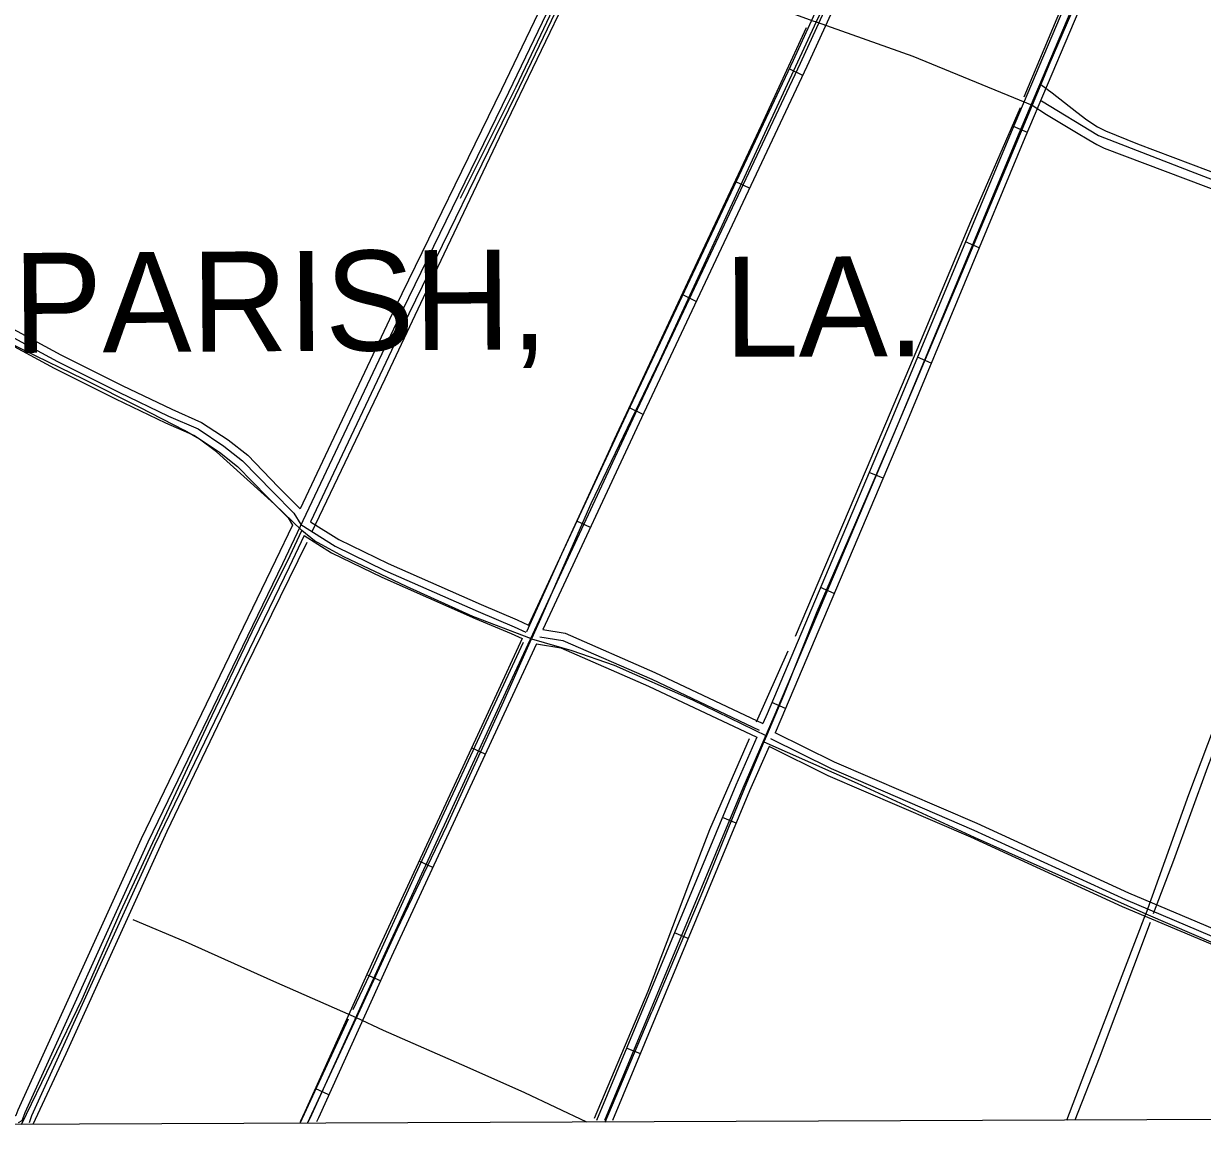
# Model space of a CAD drawing. Extents: x 3405885 to 3443815, y 558517 to 583997.
# Drawn here: x 3415002 to 3417362, y 563906 to 566129 of the extents above; entities that cross this region are included whole.
import ezdxf

# ---------------------------------------------------------------- set-up
doc = ezdxf.new("R2010")
doc.units = 0
for name, color, linetype in [('V-DTCH-CNTR', 7, 'Continuous'), ('V-GRID-FRAM', 7, 'Continuous'), ('V-ROAD-CNTR', 7, 'Continuous'), ('V-TOPO-GNAM-IDEN', 7, 'Continuous'), ('V-TOPO-SHOR', 7, 'Continuous')]:
    doc.layers.add(name, color=color, linetype=linetype)

msp = doc.modelspace()

# ---------------------------------------------------------------- linework, layer by layer
at = {"layer": 'V-DTCH-CNTR'}
for points in [[(3417302.4, 567666.9), (3417211.4, 567491.3), (3417056.5, 567153.8), (3416943.8, 566895.3), (3416932.8, 566871.6), (3416922.1, 566847.6), (3416829.7, 566641.3), (3416662.2, 566281.6), (3416589.1, 566131.9), (3416464.6, 565864), (3416275.4, 565453.5), (3416137.5, 565167.4), (3416034.5, 564931.6), (3416019, 564897.5)], [(3417610.8, 567337.5), (3417525.2, 567138.1), (3417513.3, 567110.2), (3417415.8, 566882.9), (3417344.8, 566720.2), (3417335.4, 566698.5), (3417329.4, 566685.1), (3417241.9, 566487.9), (3417145.1, 566255.7), (3417054.7, 566045.2), (3417038.6, 566006.8), (3417021.4, 565965.7), (3416973.2, 565850.9), (3416874.6, 565615.6), (3416744.7, 565309.8), (3416665.5, 565124.8), (3416590.4, 564951.7), (3416523.3, 564784.2), (3416489.2, 564703.3), (3416484.1, 564691.3), (3416445.9, 564600.6), (3416361.1, 564391.4), (3416260.1, 564151.2)], [(3416510.9, 567225.1), (3416532.6, 567208.2), (3416536.1, 567204.9), (3416539, 567198), (3416542.8, 567182.2), (3416542.3, 567172.6), (3416541, 567167.7), (3416538.4, 567160.8), (3416389.1, 566854.3), (3416219.4, 566497.9), (3416110.2, 566261.2), (3415987.6, 566001.5), (3415876.1, 565778.6)], [(3416158.8, 566298.4), (3416334.3, 566225.2), (3416582.5, 566134.3), (3416589.1, 566131.9), (3416782.1, 566063.4), (3417021.4, 565965.7)], [(3417038.6, 566006.8), (3417061.1, 565989.9), (3417110.5, 565951.2), (3417130.9, 565936.3), (3417152.1, 565922.2), (3417168.2, 565914.1)], [(3417021.4, 565965.7), (3417050.2, 565946.8), (3417110, 565910.5), (3417134.6, 565895.7), (3417150.7, 565887), (3417165.5, 565879.6), (3417409.7, 565787.1), (3417668.1, 565684.4), (3417724.1, 565659.8), (3417729.1, 565655), (3417730.5, 565653), (3417731.3, 565648.1), (3417703.1, 565563.5), (3417570.8, 565220.5), (3417461.9, 564923.1), (3417334.4, 564585.1), (3417249, 564346.9)], [(3417168.2, 565914.1), (3417231.9, 565888.3), (3417444, 565808.3)], [(3414998.3, 563925.6), (3415119.6, 564176.6), (3415196.2, 564351.2), (3415372.2, 564728.7), (3415460.1, 564911.3), (3415536.2, 565064.1), (3415559.1, 565114), (3415504.7, 565167.2), (3415388.6, 565271.4), (3415354.3, 565297.2), (3415324.5, 565314.2), (3415234.8, 565360.2), (3415121.9, 565417.4), (3415003.9, 565474.6), (3414878.6, 565537.6), (3414836.4, 565560.4), (3414707.6, 565626.3)], [(3415750.2, 564315.7), (3415849.7, 564523.2), (3415963.9, 564772.7), (3416019, 564897.5), (3415901.6, 564942), (3415768.6, 565001.9), (3415643.1, 565061.3), (3415584.9, 565093.8), (3415559.1, 565114)], [(3416019, 564897.5), (3416099.9, 564873.8), (3416184.4, 564844.8)], [(3416184.4, 564844.8), (3416341.3, 564775.5), (3416489.2, 564703.3)], [(3416484.1, 564691.3), (3416671, 564608.4), (3416905.3, 564500.6), (3417249, 564346.9), (3417436.1, 564266.3), (3417594.5, 564198.1), (3417652.8, 564172.9), (3417876.8, 564085.9), (3418078.3, 564014.4), (3418273.5, 563938.7)], [(3416129.6, 563930.1), (3416005.8, 563989), (3415889.9, 564040.4), (3415723, 564113.9), (3415668.8, 564138.7), (3415503, 564211.9), (3415326.3, 564291.3), (3415221.7, 564335.3)], [(3417090.9, 563934), (3417126.7, 564029.2), (3417249, 564346.9)], [(3415570.4, 563927.9), (3415668.8, 564138.7), (3415672.3, 564146.4), (3415750.2, 564315.7)], [(3416166.6, 563930.3), (3416260.1, 564151.2)]]:
    msp.add_lwpolyline(points, dxfattribs=at)
at = {"layer": 'V-GRID-FRAM'}
msp.add_lwpolyline([(3409954, 582088.9), (3441575.2, 582215.4), (3441655.9, 564032.2), (3410018.8, 563905.7), (3409954, 582088.9)], dxfattribs=at)
at = {"layer": 'V-ROAD-CNTR'}
for p, q in [((3416562, 566025.1), (3416534.9, 566037.9)), ((3417011.6, 565910.8), (3416984, 565922.5)), ((3416455.5, 565799), (3416428.3, 565811.7)), ((3416915.5, 565680.1), (3416887.8, 565691.6)), ((3416348.9, 565572.8), (3416321.8, 565585.6)), ((3416819.4, 565449.3), (3416791.7, 565460.8)), ((3416242.4, 565346.7), (3416215.2, 565359.4)), ((3416722.7, 565218.7), (3416695.1, 565230.4)), ((3416137, 565120), (3416109.8, 565132.7)), ((3416625.2, 564988.5), (3416597.6, 565000.2)), ((3416527.8, 564758.2), (3416500.1, 564769.9)), ((3415926.3, 564666.6), (3415899, 564679.2)), ((3416428.9, 564528.7), (3416401.2, 564540.2)), ((3415821.2, 564439.8), (3415793.9, 564452.4)), ((3416332.9, 564297.9), (3416305.2, 564309.4)), ((3415716.5, 564212.9), (3415689.2, 564225.3)), ((3416236.9, 564067.1), (3416209.2, 564078.6)), ((3415613.4, 563985.1), (3415586.1, 563997.5))]:
    msp.add_line(p, q, dxfattribs=at)
for points in [[(3418009.6, 568256.7), (3417948.1, 568084), (3417784.8, 567724.8), (3417633.8, 567379), (3417470.5, 567008.8), (3417261.3, 566539.3), (3416993.1, 565905.5), (3416751, 565323.9), (3416504.4, 564741.6), (3416441.9, 564598.9), (3416165.1, 563933.5)], [(3418023.8, 568251.7), (3417962.1, 568078.4), (3417798.5, 567718.7), (3417647.5, 567372.9), (3417484.2, 567002.8), (3417275.1, 566533.4), (3417006.9, 565899.7), (3416764.8, 565318.1), (3416518.2, 564735.7), (3416506.7, 564709.5)], [(3415779.8, 567653.6), (3415947.5, 567565.5), (3416277.7, 567377), (3416503.8, 567239.2), (3416549.6, 567203.3), (3416538.7, 567159.5), (3416392.9, 566873), (3416158.2, 566377.3), (3415972.7, 565990.5), (3415759.9, 565554.1), (3415520.2, 565047.4), (3415251, 564490.5), (3415004.4, 563948.6), (3414999, 563932.9), (3414991.3, 563928.8)], [(3417300.7, 567666.7), (3417148.8, 567344.9), (3416899.5, 566797.7), (3416556.6, 566048.8), (3416230.4, 565356.4), (3415958.4, 564771.7), (3415725.1, 564268), (3415578.7, 563944.9), (3415572.2, 563931.1)], [(3417282.4, 567663.1), (3417135.2, 567351.2), (3416885.8, 566804), (3416543, 566055.1), (3416216.8, 565362.7), (3416013.2, 564925)], [(3417306.3, 567643.4), (3417162.4, 567338.6), (3416913.1, 566791.5), (3416570.2, 566042.5), (3416244, 565350), (3416042, 564915.8)], [(3417653.7, 567462.1), (3417620.1, 567385), (3417456.8, 567014.9), (3417247.5, 566545.3), (3416979.3, 565911.3), (3416737.1, 565329.7), (3416490.6, 564747.5), (3416482.2, 564728.2)], [(3416105.9, 566302.9), (3415959.2, 565997), (3415746.4, 565560.6), (3415555.7, 565157.6)], [(3416139.1, 566302.7), (3415986.2, 565984), (3415773.4, 565547.6), (3415576.7, 565131.7)], [(3414721.7, 565627.2), (3414775.7, 565603.8), (3414918.1, 565534.7), (3415070.2, 565452.7), (3415192.8, 565391), (3415292.6, 565343.2), (3415351.4, 565317.4), (3415403, 565283.3), (3415440.7, 565253.7), (3415501.4, 565191.3), (3415543.5, 565148.6), (3415556.9, 565126.5), (3415626, 565082.7), (3415725.7, 565034.5), (3415912.4, 564952.1), (3415984.4, 564921.5), (3416007.8, 564910.9)], [(3414730.8, 565639.6), (3414781.9, 565617.4), (3414924.9, 565548), (3415077.1, 565466), (3415199.4, 565404.5), (3415298.9, 565356.8), (3415358.6, 565330.6), (3415411.8, 565295.5), (3415450.8, 565264.8), (3415512.1, 565201.8), (3415555.7, 565157.6)], [(3414717, 565612.9), (3414769.4, 565590.2), (3414911.2, 565521.3), (3415063.2, 565439.4), (3415186.2, 565377.6), (3415286.4, 565329.6), (3415344.2, 565304.2), (3415394.3, 565271.1), (3415430.7, 565242.5), (3415490.7, 565180.8), (3415531.6, 565139.3), (3415540.3, 565125)], [(3415576.7, 565131.7), (3415633.3, 565095.9), (3415732, 565048.1), (3415918.4, 564965.9), (3415990.4, 564935.2), (3416013.2, 564925)], [(3415540.3, 565125), (3415506.6, 565053.9), (3415237.4, 564496.9), (3414990.4, 563954.2), (3414986.7, 563943.3), (3414984.2, 563942)], [(3415563.7, 565104.4), (3415533.7, 565040.9), (3415264.6, 564484.2), (3415018.3, 563943.1), (3415013.4, 563928.9)], [(3415563.7, 565104.4), (3415618.7, 565069.6), (3415719.4, 565020.9), (3415906.4, 564938.3), (3415978.3, 564907.8), (3416000.5, 564897.8)], [(3416042, 564915.8), (3416086.3, 564908.5), (3416265.9, 564830.1), (3416482.2, 564728.2)], [(3416000.5, 564897.8), (3415944.8, 564778), (3415711.4, 564274.3), (3415565.1, 563951.2), (3415555.6, 563931)], [(3416035.8, 564901.6), (3416082, 564894), (3416259.7, 564816.4), (3416474.9, 564715)], [(3416028.9, 564887.6), (3415972, 564765.4), (3415738.7, 564261.8), (3415592.3, 563938.6), (3415588.8, 563931.2)], [(3416028.9, 564887.6), (3416077.7, 564879.5), (3416253.5, 564802.8), (3416470.1, 564700.7)], [(3417591, 564231.3), (3417506.9, 564265.1), (3417214.5, 564388.7), (3416911, 564527.9), (3416625.6, 564650.8), (3416506.7, 564709.5)], [(3416470.1, 564700.7), (3416428.1, 564604.8), (3416148.8, 563933.4)], [(3416494.7, 564682), (3416455.7, 564593), (3416181.4, 563933.5)], [(3417580.9, 564203.1), (3417495.5, 564237.4), (3417202.4, 564361.3), (3416898.8, 564500.5), (3416613.1, 564623.6), (3416494.7, 564682)], [(3417589.7, 564215.7), (3417501.2, 564251.3), (3417208.5, 564375), (3416904.9, 564514.2), (3416619.3, 564637.2), (3416498, 564697)]]:
    msp.add_lwpolyline(points, dxfattribs=at)
at = {"layer": 'V-TOPO-SHOR'}
msp.add_line((3416532.4, 564873), (3416468.9, 564730.6), dxfattribs=at)
for points in [[(3417311, 566686.8), (3417195.7, 566425.9), (3417102.2, 566214.1), (3417004.4, 565981.6)], [(3416189.8, 566395.8), (3416098.4, 566200.3), (3415961.2, 565914.3), (3415824.3, 565626.5), (3415725.5, 565417), (3415579, 565111.4)], [(3417958.5, 566199.4), (3417762, 565668.3), (3417757.8, 565657), (3417561.6, 565140.5), (3417485.3, 564935.2), (3417372.4, 564640.3), (3417304.4, 564453.7), (3417263.8, 564347.4)], [(3416180.2, 565287.1), (3416341.5, 565631.1), (3416479.1, 565925.3), (3416569.2, 566121)], [(3416997.5, 565960.2), (3416897.9, 565732.1), (3416797.5, 565493), (3416688.8, 565236.4), (3416546.5, 564901.9)], [(3417039.8, 565974.2), (3417153.9, 565905), (3417338.1, 565833.3), (3417527.3, 565760.3), (3417762, 565668.3)], [(3416180.2, 565287.1), (3416082.4, 565074.5), (3416009.1, 564911.4)], [(3415569.4, 565090.2), (3415444.9, 564837.6), (3415289.1, 564511.6), (3415086.5, 564067.2), (3415020.9, 563925.7)], [(3416002.4, 564890.2), (3415910.5, 564692.3), (3415786, 564424.9), (3415694.5, 564224.8), (3415661, 564154.8)], [(3416454.7, 564697), (3416375.5, 564515.1), (3416333.1, 564405.6), (3416289.7, 564291.1), (3416252.1, 564191.6), (3416144.7, 563937.5)], [(3417257.5, 564329.7), (3417155.2, 564058), (3417106.8, 563934.1)], [(3415652, 564136.3), (3415555.2, 563927.8)]]:
    msp.add_lwpolyline(points, dxfattribs=at)

# ---------------------------------------------------------------- texts
at = {"layer": 'V-TOPO-GNAM-IDEN'}
for s, rotation, p in [('PARISH,', 0.3949, (3414982, 565469.5)), ('LA.', 0.1859, (3416405.3, 565461.8))]:
    msp.add_text(s, height=200, rotation=rotation, dxfattribs=at).set_placement(p)

doc.saveas('drawing.dxf')
